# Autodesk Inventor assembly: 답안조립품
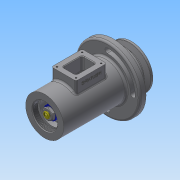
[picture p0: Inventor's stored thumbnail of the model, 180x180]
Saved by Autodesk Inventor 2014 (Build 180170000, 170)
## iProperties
Created: 2017-05
Part Number: 답안조립품
Document SubType Name: Assembly
Designer: SCD-A14
Author: SCD-A14
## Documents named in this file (17)
- C:\Users\SCD-A14\Desktop\470508V1008\답안조립품.iam
- C:\Users\SCD-A14\Desktop\470508V1008\본체.ipt
- C:\Users\SCD-A14\Desktop\470508V1008\사이드 커버.ipt
- 사이드 커버.ipt
- C:\Users\SCD-A14\Desktop\470508V1008\축.ipt
- C:\Users\SCD-A14\Desktop\470508V1008\부시1.ipt
- C:\Users\SCD-A14\Desktop\470508V1008\베어링 15 x 35 x 11.ipt
- C:\Users\SCD-A14\Desktop\470508V1008\멈춤링 35x1.6.ipt
- C:\Users\SCD-A14\Desktop\470508V1008\부시2.ipt
- C:\Users\SCD-A14\Desktop\470508V1008\와셔 10x21.ipt
- C:\Users\SCD-A14\Desktop\470508V1008\너트 M10.ipt
- C:\Users\SCD-A14\Desktop\470508V1008\멈춤링 15 x 1.ipt
- C:\Users\SCD-A14\Desktop\470508V1008\오일 실 15 25 7.ipt
- C:\Users\SCD-A14\Desktop\470508V1008\V-벨트풀리.ipt
- C:\Users\SCD-A14\Desktop\470508V1008\키 4 x 4 x 18.ipt
- C:\Users\SCD-A14\Desktop\470508V1008\와셔 4x16.ipt
- C:\Users\SCD-A14\Desktop\470508V1008\볼트 M4 x 10.ipt
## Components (2 placed, 2 different names)
1. V-벨트풀리:1 — 각도:2
2. ISO 4017 M4 x 10:1
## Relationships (1: Angle 1)
- 각도:2 [Angle]: V-벨트풀리:1
